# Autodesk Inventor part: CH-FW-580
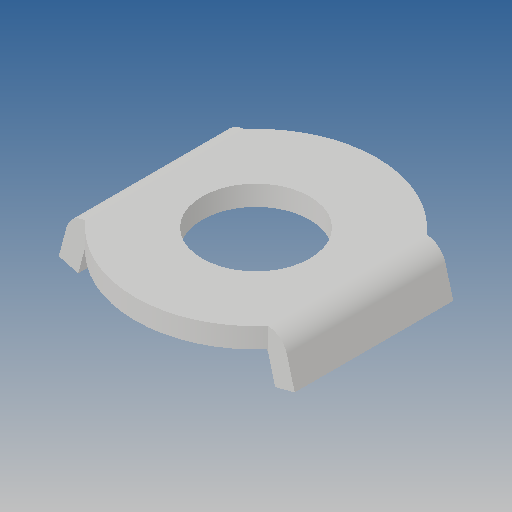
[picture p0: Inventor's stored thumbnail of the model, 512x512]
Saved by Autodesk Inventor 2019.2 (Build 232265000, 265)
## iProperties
Created: 2012-09
Part Number: CH-FW-580
Material: Ogólny
Document SubType Name: Modeling
Designer: CADENGINEERING4
Density: 1 g/cm^3
Appearance: Domyślna
Author: CADENGINEERING4
Revision Number: ÈÎºÎ
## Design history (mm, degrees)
feature "ÇÐ³ý-À­Éì1"
node "Bryła1"
